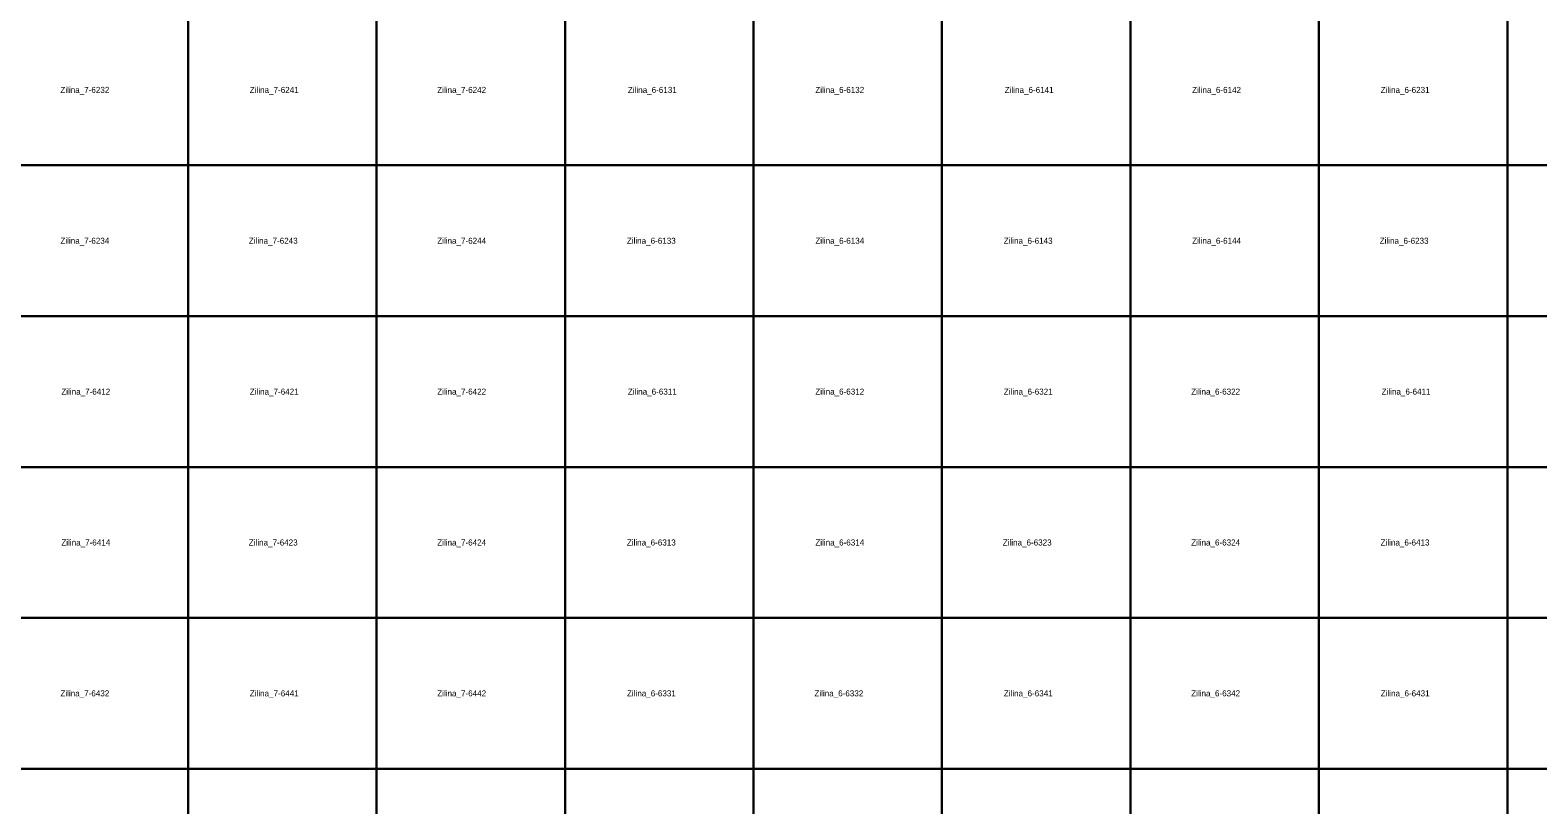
# Model space of a CAD drawing. Extents: x -445938 to -437812, y -1177250 to -1169500.
# Drawn here: x -443387 to -440887, y -1173810 to -1172526 of the extents above; entities that cross this region are included whole.
import ezdxf

# ---------------------------------------------------------------- set-up
doc = ezdxf.new("R2010")
doc.units = 0
doc.layers.add('Vrstva 4', color=7, linetype='Continuous')
doc.layers.add('Vrstva 6', color=7, linetype='Continuous')

msp = doc.modelspace()

# ---------------------------------------------------------------- linework, layer by layer
at = {"layer": 'Vrstva 4'}
for points in [[(-443125, -1172500), (-443125, -1172750), (-443437.5, -1172750), (-443437.5, -1172500)], [(-442812.5, -1172500), (-442812.5, -1172750), (-443125, -1172750), (-443125, -1172500)], [(-442500, -1172500), (-442500, -1172750), (-442812.5, -1172750), (-442812.5, -1172500)], [(-442187.5, -1172500), (-442187.5, -1172750), (-442500, -1172750), (-442500, -1172500)], [(-441875, -1172500), (-441875, -1172750), (-442187.5, -1172750), (-442187.5, -1172500)], [(-441562.5, -1172500), (-441562.5, -1172750), (-441875, -1172750), (-441875, -1172500)], [(-441250, -1172500), (-441250, -1172750), (-441562.5, -1172750), (-441562.5, -1172500)], [(-440937.5, -1172500), (-440937.5, -1172750), (-441250, -1172750), (-441250, -1172500)], [(-440625, -1172500), (-440625, -1172750), (-440937.5, -1172750), (-440937.5, -1172500)], [(-443125, -1172750), (-443125, -1173000), (-443437.5, -1173000), (-443437.5, -1172750)], [(-442812.5, -1172750), (-442812.5, -1173000), (-443125, -1173000), (-443125, -1172750)], [(-442500, -1172750), (-442500, -1173000), (-442812.5, -1173000), (-442812.5, -1172750)], [(-442187.5, -1172750), (-442187.5, -1173000), (-442500, -1173000), (-442500, -1172750)], [(-441875, -1172750), (-441875, -1173000), (-442187.5, -1173000), (-442187.5, -1172750)], [(-441562.5, -1172750), (-441562.5, -1173000), (-441875, -1173000), (-441875, -1172750)], [(-441250, -1172750), (-441250, -1173000), (-441562.5, -1173000), (-441562.5, -1172750)], [(-440937.5, -1172750), (-440937.5, -1173000), (-441250, -1173000), (-441250, -1172750)], [(-440625, -1172750), (-440625, -1173000), (-440937.5, -1173000), (-440937.5, -1172750)], [(-443125, -1173000), (-443125, -1173250), (-443437.5, -1173250), (-443437.5, -1173000)], [(-442812.5, -1173000), (-442812.5, -1173250), (-443125, -1173250), (-443125, -1173000)], [(-442500, -1173000), (-442500, -1173250), (-442812.5, -1173250), (-442812.5, -1173000)], [(-442187.5, -1173000), (-442187.5, -1173250), (-442500, -1173250), (-442500, -1173000)], [(-441875, -1173000), (-441875, -1173250), (-442187.5, -1173250), (-442187.5, -1173000)], [(-441562.5, -1173000), (-441562.5, -1173250), (-441875, -1173250), (-441875, -1173000)], [(-441250, -1173000), (-441250, -1173250), (-441562.5, -1173250), (-441562.5, -1173000)], [(-440937.5, -1173000), (-440937.5, -1173250), (-441250, -1173250), (-441250, -1173000)], [(-440625, -1173000), (-440625, -1173250), (-440937.5, -1173250), (-440937.5, -1173000)], [(-443125, -1173250), (-443125, -1173500), (-443437.5, -1173500), (-443437.5, -1173250)], [(-442812.5, -1173250), (-442812.5, -1173500), (-443125, -1173500), (-443125, -1173250)], [(-442500, -1173250), (-442500, -1173500), (-442812.5, -1173500), (-442812.5, -1173250)], [(-442187.5, -1173250), (-442187.5, -1173500), (-442500, -1173500), (-442500, -1173250)], [(-441875, -1173250), (-441875, -1173500), (-442187.5, -1173500), (-442187.5, -1173250)], [(-441562.5, -1173250), (-441562.5, -1173500), (-441875, -1173500), (-441875, -1173250)], [(-441250, -1173250), (-441250, -1173500), (-441562.5, -1173500), (-441562.5, -1173250)], [(-440937.5, -1173250), (-440937.5, -1173500), (-441250, -1173500), (-441250, -1173250)], [(-440625, -1173250), (-440625, -1173500), (-440937.5, -1173500), (-440937.5, -1173250)], [(-443125, -1173500), (-443125, -1173750), (-443437.5, -1173750), (-443437.5, -1173500)], [(-442812.5, -1173500), (-442812.5, -1173750), (-443125, -1173750), (-443125, -1173500)], [(-442500, -1173500), (-442500, -1173750), (-442812.5, -1173750), (-442812.5, -1173500)], [(-442187.5, -1173500), (-442187.5, -1173750), (-442500, -1173750), (-442500, -1173500)], [(-441875, -1173500), (-441875, -1173750), (-442187.5, -1173750), (-442187.5, -1173500)], [(-441562.5, -1173500), (-441562.5, -1173750), (-441875, -1173750), (-441875, -1173500)], [(-441250, -1173500), (-441250, -1173750), (-441562.5, -1173750), (-441562.5, -1173500)], [(-440937.5, -1173500), (-440937.5, -1173750), (-441250, -1173750), (-441250, -1173500)], [(-440625, -1173500), (-440625, -1173750), (-440937.5, -1173750), (-440937.5, -1173500)], [(-443125, -1173750), (-443125, -1174000), (-443437.5, -1174000), (-443437.5, -1173750)], [(-442812.5, -1173750), (-442812.5, -1174000), (-443125, -1174000), (-443125, -1173750)], [(-442500, -1173750), (-442500, -1174000), (-442812.5, -1174000), (-442812.5, -1173750)], [(-442187.5, -1173750), (-442187.5, -1174000), (-442500, -1174000), (-442500, -1173750)], [(-441875, -1173750), (-441875, -1174000), (-442187.5, -1174000), (-442187.5, -1173750)], [(-441562.5, -1173750), (-441562.5, -1174000), (-441875, -1174000), (-441875, -1173750)], [(-441250, -1173750), (-441250, -1174000), (-441562.5, -1174000), (-441562.5, -1173750)], [(-440937.5, -1173750), (-440937.5, -1174000), (-441250, -1174000), (-441250, -1173750)], [(-440625, -1173750), (-440625, -1174000), (-440937.5, -1174000), (-440937.5, -1173750)]]:
    msp.add_lwpolyline(points, close=True, dxfattribs=at)

# ---------------------------------------------------------------- texts
at = {"layer": 'Vrstva 6'}
for s, p in [('Zilina_7-6232', (-443336.796, -1172630)), ('Zilina_7-6241', (-443022.76, -1172630)), ('Zilina_7-6242', (-442711.954, -1172630)), ('Zilina_6-6131', (-442395.793, -1172630)), ('Zilina_6-6132', (-442084.986, -1172630)), ('Zilina_6-6141', (-441770.95, -1172630)), ('Zilina_6-6142', (-441460.144, -1172630)), ('Zilina_6-6231', (-441147.486, -1172630)), ('Zilina_7-6234', (-443336.796, -1172880)), ('Zilina_7-6243', (-443024.454, -1172880)), ('Zilina_7-6244', (-442711.954, -1172880)), ('Zilina_6-6133', (-442397.486, -1172880)), ('Zilina_6-6134', (-442084.986, -1172880)), ('Zilina_6-6143', (-441772.644, -1172880)), ('Zilina_6-6144', (-441460.144, -1172880)), ('Zilina_6-6233', (-441149.178, -1172880)), ('Zilina_7-6412', (-443335.261, -1173130)), ('Zilina_7-6421', (-443022.76, -1173130)), ('Zilina_7-6422', (-442711.954, -1173130)), ('Zilina_6-6311', (-442395.793, -1173130)), ('Zilina_6-6312', (-442084.986, -1173130)), ('Zilina_6-6321', (-441772.486, -1173130)), ('Zilina_6-6322', (-441461.678, -1173130)), ('Zilina_6-6411', (-441145.95, -1173130)), ('Zilina_7-6414', (-443335.261, -1173380)), ('Zilina_7-6423', (-443024.454, -1173380)), ('Zilina_7-6424', (-442711.954, -1173380)), ('Zilina_6-6313', (-442397.486, -1173380)), ('Zilina_6-6314', (-442084.986, -1173380)), ('Zilina_6-6323', (-441774.178, -1173380)), ('Zilina_6-6324', (-441461.678, -1173380)), ('Zilina_6-6413', (-441147.644, -1173380)), ('Zilina_7-6432', (-443336.796, -1173630)), ('Zilina_7-6441', (-443022.76, -1173630)), ('Zilina_7-6442', (-442711.954, -1173630)), ('Zilina_6-6331', (-442397.328, -1173630)), ('Zilina_6-6332', (-442086.521, -1173630)), ('Zilina_6-6341', (-441772.486, -1173630)), ('Zilina_6-6342', (-441461.678, -1173630)), ('Zilina_6-6431', (-441147.486, -1173630))]:
    msp.add_text(s, height=10, dxfattribs=at).set_placement(p)

doc.saveas('drawing.dxf')
